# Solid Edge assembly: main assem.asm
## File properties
Author: Robert a Rhodes jr
Template: Normal.asm
Last saved by: Cadcim
Revision: 13
Application: Solid Edge
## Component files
master rod.par
piston.par
piston pin.par
arti subassm.asm
piston pin plug.par
piston ring.par
master rod bearing.par
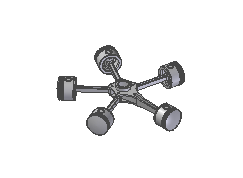
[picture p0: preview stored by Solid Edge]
